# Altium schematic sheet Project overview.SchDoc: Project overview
size A4; Date: Not used; ApprovedBy: Not used; CheckedBy: Not used; Author: Not used; CompanyName: STMicroelectronics; DrawnBy: Not used; Engineer: Not used; Organization: Not used; Address1: Not used; Address2: Not used; Address3: Not used; Address4: Not used; DocumentNumber: 2; Revision: Not used; SheetNumber: 1; SheetTotal: 19
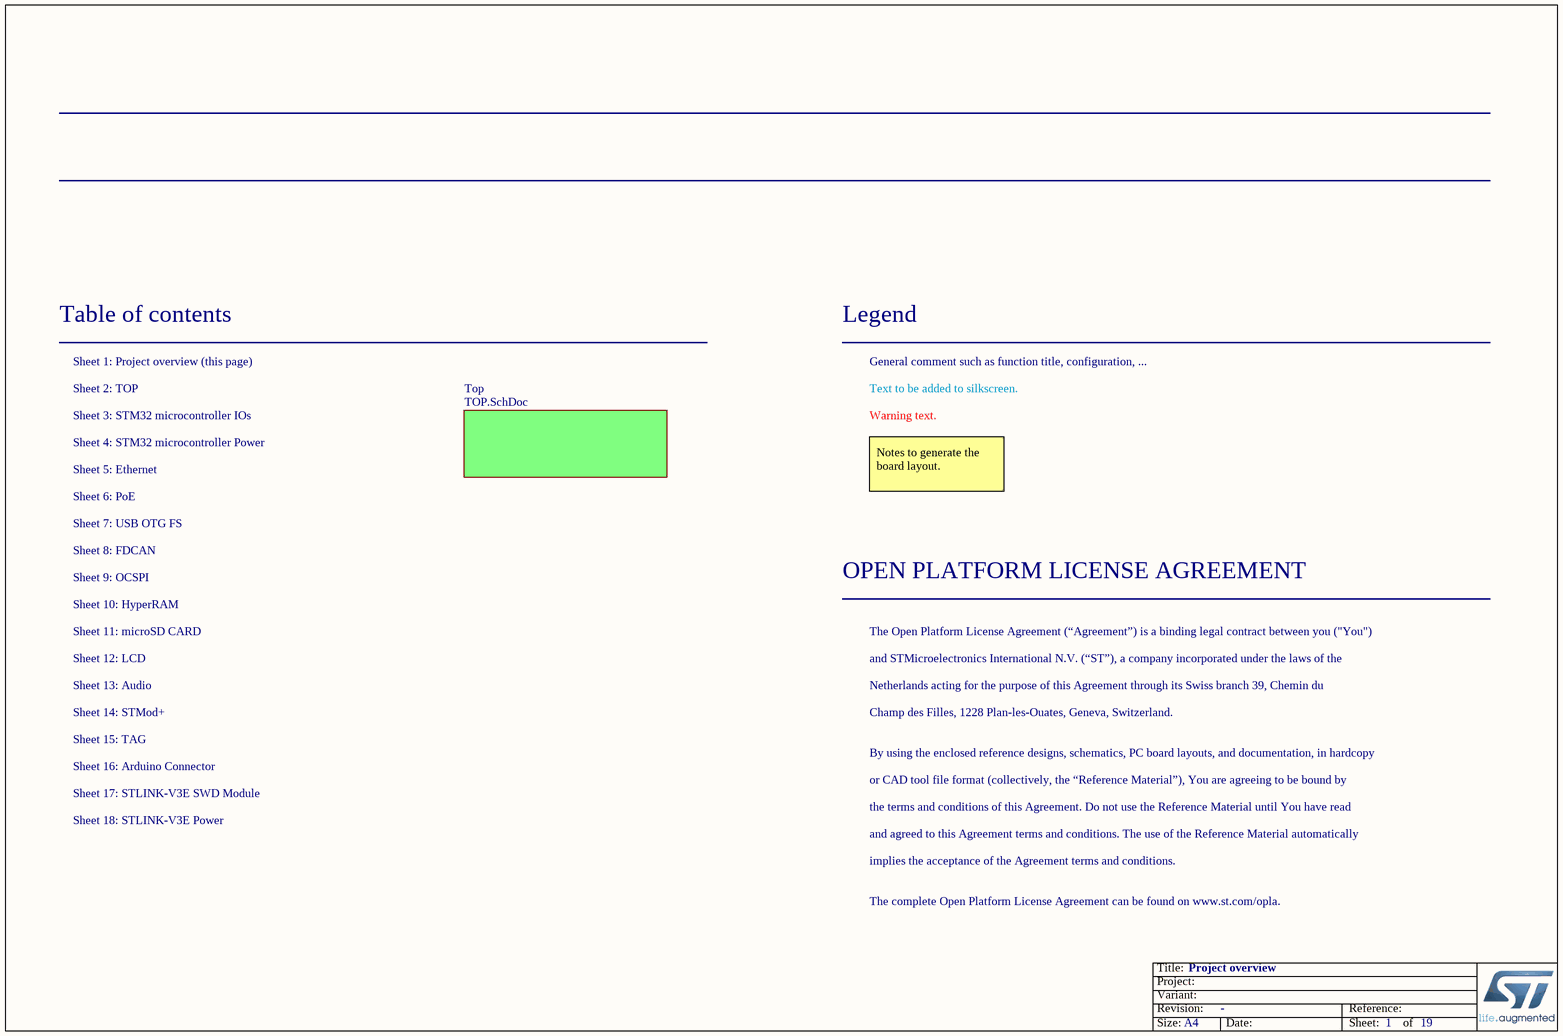
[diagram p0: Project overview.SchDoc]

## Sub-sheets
Top = TOP.SchDoc: no entries

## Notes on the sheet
- Table of contents
- Sheet 1: Project overview (this page)
- Legend
- General comment such as function title, configuration, ...
- Sheet 2: TOP
- Sheet 4: STM32 microcontroller Power
- Sheet 3: STM32 microcontroller IOs
- Text to be added to silkscreen.
- Warning text.
- Sheet 6: PoE
- Sheet 5: Ethernet
- Notes to generate the board layout.
- Sheet 8: FDCAN
- Sheet 7: USB OTG FS
- Sheet 9: OCSPI
- OPEN PLATFORM LICENSE AGREEMENT
- Sheet 10: HyperRAM
- Sheet 11: microSD CARD
- The Open Platform License Agreement (“Agreement”) is a binding legal contract between you ("You")
- Sheet 12: LCD
- Sheet 14: STMod+
- Sheet 13: Audio
- and STMicroelectronics International N.V. (“ST”), a company incorporated under the laws of the
- Netherlands acting for the purpose of this Agreement through its Swiss branch 39, Chemin du
- Champ des Filles, 1228 Plan-les-Ouates, Geneva, Switzerland.
- Sheet 16: Arduino Connector
- Sheet 15: TAG
- By using the enclosed reference designs, schematics, PC board layouts, and documentation, in hardcopy
- or CAD tool file format (collectively, the “Reference Material”), You are agreeing to be bound by
- Sheet 18: STLINK-V3E Power
- Sheet 17: STLINK-V3E SWD Module
- the terms and conditions of this Agreement. Do not use the Reference Material until You have read
- and agreed to this Agreement terms and conditions. The use of the Reference Material automatically
- implies the acceptance of the Agreement terms and conditions.
- The complete Open Platform License Agreement can be found on www.st.com/opla.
